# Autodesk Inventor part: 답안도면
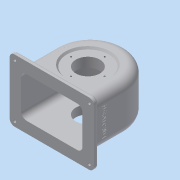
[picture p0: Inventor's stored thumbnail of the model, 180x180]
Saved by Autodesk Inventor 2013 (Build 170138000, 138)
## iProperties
Created: 2016-01
Part Number: 답안도면
Material: 일반
Document SubType Name: Modeling
Designer: Administrator
Density: 1 g/cm^3
Author: Administrator
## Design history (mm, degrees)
sketch "스케치1"
  geometry: L1 (-51, 0)-(-51, -64); L2 (51, 0)-(51, -64); L3 (-57, -64)-(-57, 0); L4 (57, 0)-(57, -64); L5 (-57, -64)-(-51, -64); L6 (51, -64)-(57, -64); A1 r 51 centre (0, 0) between (51, 0) and (-51, 0); A2 r 57 centre (0, 0) between (57, 0) and (-57, 0); 1 further point
  constraints: 12 end point, 4 point on circle, 2 centre point, 2 parallel, 2 perpendicular, 2 tangent, 1 coincident, 1 collinear, 1 vertical
  dimensions: "d0" = 102 diameter of A1; "d2" = 6 distance between parallel lines of L3 L1; "d4" = 6 radial gap between concentric circles of A1 A2; "d6" = 64 vertical distance of L4.end point (0, 0); "d7" = 6 distance between parallel lines of L2 L4
extrude "돌출1" new body sketch "스케치1" stored distance "d8" = 77; taper "d9" = 0 deg
sketch "스케치2"
  geometry: L1 (-51, -64)-(-51, 0) reference; L2 (51, 0)-(51, -64) reference; L3 (-51, -64)-(-46.848, -64); L4 (-46.848, -64)-(51, -64); A1 r 51 centre (0, 0) between (51, 0) and (-51, 0) reference; 1 further point
  constraints: 4 end point, 1 collinear
extrude "돌출2" join sketch "스케치2" distance "d10" = 5; taper "d11" = 0 deg
sketch "스케치3"
  geometry: L1 (51, 0)-(51, -64) reference; L2 (51, -64)-(57, -64) reference; L3 (57, -64)-(57, 0) reference; L4 (-57, 0)-(-57, -64) reference; L5 (-57, -64)-(-51, -64) reference; L6 (-51, -64)-(-51, 0) reference; L7 (-51, -64)-(51, -64); A1 r 51 centre (0, 0) between (51, 0) and (-51, 0) reference; A2 r 57 centre (0, 0) between (57, 0) and (-57, 0) reference; 1 further point
  constraints: 2 end point, 1 perpendicular
extrude "돌출3" join sketch "스케치3" distance "d12" = 5; taper "d13" = 0 deg
sketch "스케치5"
  geometry: L1 (-57, -64)-(57, -64) reference; C1 r 31 at (0, -4); A1 r 57 centre (0, 0) between (57, 0) and (-57, 0) reference; 1 further point
  constraints: 1 centre point, 1 vertical alignment
  dimensions: "d89" = 62 diameter of C1; "d91" = 60 distance from line of L1 C1.centre
extrude "돌출4" join sketch "스케치5" distance "d25" = 10; taper "d26" = 0 deg
sketch "스케치6"
  geometry: L1 (127, 90.5)-(-13, 90.5); L2 (-13, 90.5)-(-13, -13.5); L3 (-13, -13.5)-(127, -13.5); L4 (127, -13.5)-(127, 90.5); L5 (0, 77)-(114, 77) reference; L6 (114, 0)-(114, 77) reference; L7 (114, 0)-(0, 0) reference; L8 (0, 0)-(0, 77) reference; 1 further point
  constraints: 8 end point, 2 parallel, 1 horizontal, 1 perpendicular
  dimensions: "d27" = 140 distance of L2.end L3.end; "d29" = 104 distance of L3.end L1.start; "d30" = 70 distance from line of point (57, 38.5) L4; "d31" = 52 distance from line of L1 point (57, 38.5)
fillet "모깎기1" dims "d34" = 9
extrude "돌출7" join sketch "스케치6" distance "d48" = 7; taper "d49" = 0 deg
fillet "모깎기4" dims "d50" = 14
fillet "모깎기5" dims "d73" = 8
fillet "모깎기6" dims "d74" = 3
sketch "스케치11"
  geometry: L1 (124, 104)-(0, 104) reference; L2 (-8, 96)-(-8, 8) reference; L3 (0, 0)-(124, 0) reference; L4 (132, 8)-(132, 96) reference; C1 r 2.5 at (0, 96); C2 r 2.5 at (0, 8); C3 r 2.5 at (124, 8); C4 r 2.5 at (124, 96); A1 r 8 centre (0, 96) between (0, 104) and (-8, 96) reference; A2 r 8 centre (0, 8) between (-8, 8) and (0, 0) reference; A3 r 8 centre (124, 8) between (124, 0) and (132, 8) reference; A4 r 8 centre (124, 96) between (132, 96) and (124, 104) reference; 1 further point
  constraints: 4 centre point, 4 coincident
  dimensions: "d75" = 5 diameter of C1; "d77" = 5 diameter of C4; "d78" = 5 diameter of C3; "d79" = 5 diameter of C2
sketch "스케치12"
  geometry: L1 (-57, 38.5)-(0, 38.5) reference; L2 (0, 33.5)-(-64, 33.5) reference; L3 (-64, -44)-(-64, 44) reference; L4 (-4, 38.5)-(-4, 19.5); L5 (-4, 19.5)-(24, 19.5); L6 (24, 19.5)-(39.943, 38.5); L7 (0, 38.5)-(43, 38.5) reference; L8 (16, 19.5)-(16, 35.5); L9 (16, 35.5)-(30.899, 35.5); L10 (30.899, 35.5)-(33.416, 38.5); L11 (39.943, 38.5)-(33.416, 38.5); L12 (33.416, 38.5)-(-4, 38.5); 1 further point
  constraints: 16 end point, 4 point on line, 3 parallel, 3 perpendicular
  dimensions: "d80" = 19 distance between parallel lines of L1 L5; "d81" = 50 deg angle of L5 L6; "d82" = 5 distance between parallel lines of L10 L6; "d83" = 60 distance between parallel lines of L3 L4; "d84" = 28 distance from line of L4 L5.end; "d85" = 16 distance of L8.start L8.end; "d86" = 20 distance between parallel lines of L4 L8
revolve "회전3" stored, may be unused: angle "d87" = 90 deg
revolve "회전4" stored, may be unused: angle "d88" = 90 deg
sketch "스케치13"
  geometry: C1 r 31 at (0, 0) reference; A1 r 24 centre (0, 0) between (0, 24) and (0, -24); 5 further points
  constraints: 4 point on circle, 3 coincident, 2 horizontal alignment, 2 vertical alignment, 1 centre point
  dimensions: "d92" = 48 diameter of A1
hole "구멍4" sketch "스케치13" at (-24, 0), (0, 24), (0, -24), (24, 0) diameter "d94" = 2.459; stored, may be unused: countersink angle "d98" = 90 deg, drill point angle "d100" = 118 deg; dims "d95" = 6, "d96" = 4, "d97" = 2, "d99" = 8
sketch "스케치14"
  geometry: C1 r 34.899 at (0, 0) reference; C2 r 20 at (0, 0) reference; A1 r 28 centre (0, 0) between (0, 28) and (-28, 0); 3 further points
  constraints: 4 point on circle, 2 horizontal alignment, 1 centre point, 1 coincident, 1 vertical alignment
  dimensions: "d101" = 56 diameter of A1
hole "구멍5" sketch "스케치14" at (0, 28), (28, 0), (0, -28), (-28, 0) diameter "d103" = 2.459; stored, may be unused: countersink angle "d107" = 90 deg, drill point angle "d109" = 118 deg; dims "d104" = 7, "d105" = 4, "d106" = 2, "d108" = 9
hole "구멍6" diameter "d112" = 40; stored, may be unused: countersink angle "d116" = 90 deg, drill point angle "d118" = 0 deg; dims "d113" = 40, "d114" = 4, "d115" = 2, "d117" = 20, "d144" = 10, "d145" = 10
node "작업 평면1"
sketch "스케치15"
  geometry: C1 r 6 at (62, 52); 1 further point
  constraints: 1 centre point, 1 coincident
  dimensions: "d120" = 12 diameter of C1
extrude "돌출8" join sketch "스케치15" distance "d122" = 7; taper "d123" = 0 deg
hole "구멍7" diameter "d126" = 4.459; stored, may be unused: countersink angle "d130" = 90 deg, drill point angle "d132" = 0 deg; dims "d124" = 10, "d125" = 10, "d127" = 15, "d128" = 4, "d129" = 2, "d131" = 15
sketch "스케치16"
  geometry: L1 (-14, 43.946)-(-14, 0) reference; L2 (68.5, -7)-(-19.5, -7) reference; 2 further points
  constraints: 1 other
  dimensions: "d133" = 38.5 distance from line of L1 point (24.5, 23); "d134" = 30 distance from line of L2 point (24.5, 23)
feature "엠보싱1" sketch "스케치16" dims "d0" = 102, "d2" = 6, "d4" = 6, "d6" = 64, "d7" = 6, "d135" = 0.5, "d136" = 0
fillet "모깎기7" dims "d137" = 3
fillet "모깎기8" dims "d138" = 3
fillet "모깎기9" dims "d139" = 1
extrude "돌출10" cut sketch "스케치11" distance "d142" = 7; taper "d143" = 0 deg
chamfer "모따기1" distance "d146" = 1; stored, may be unused: second distance "d147" = 2, angle "d148" = 45 deg
node "솔리드1"
node "투영된 루프1"
node "투영된 루프3"
other parameters: "d3" = 64, "d20" = 62, "d119" = -127
